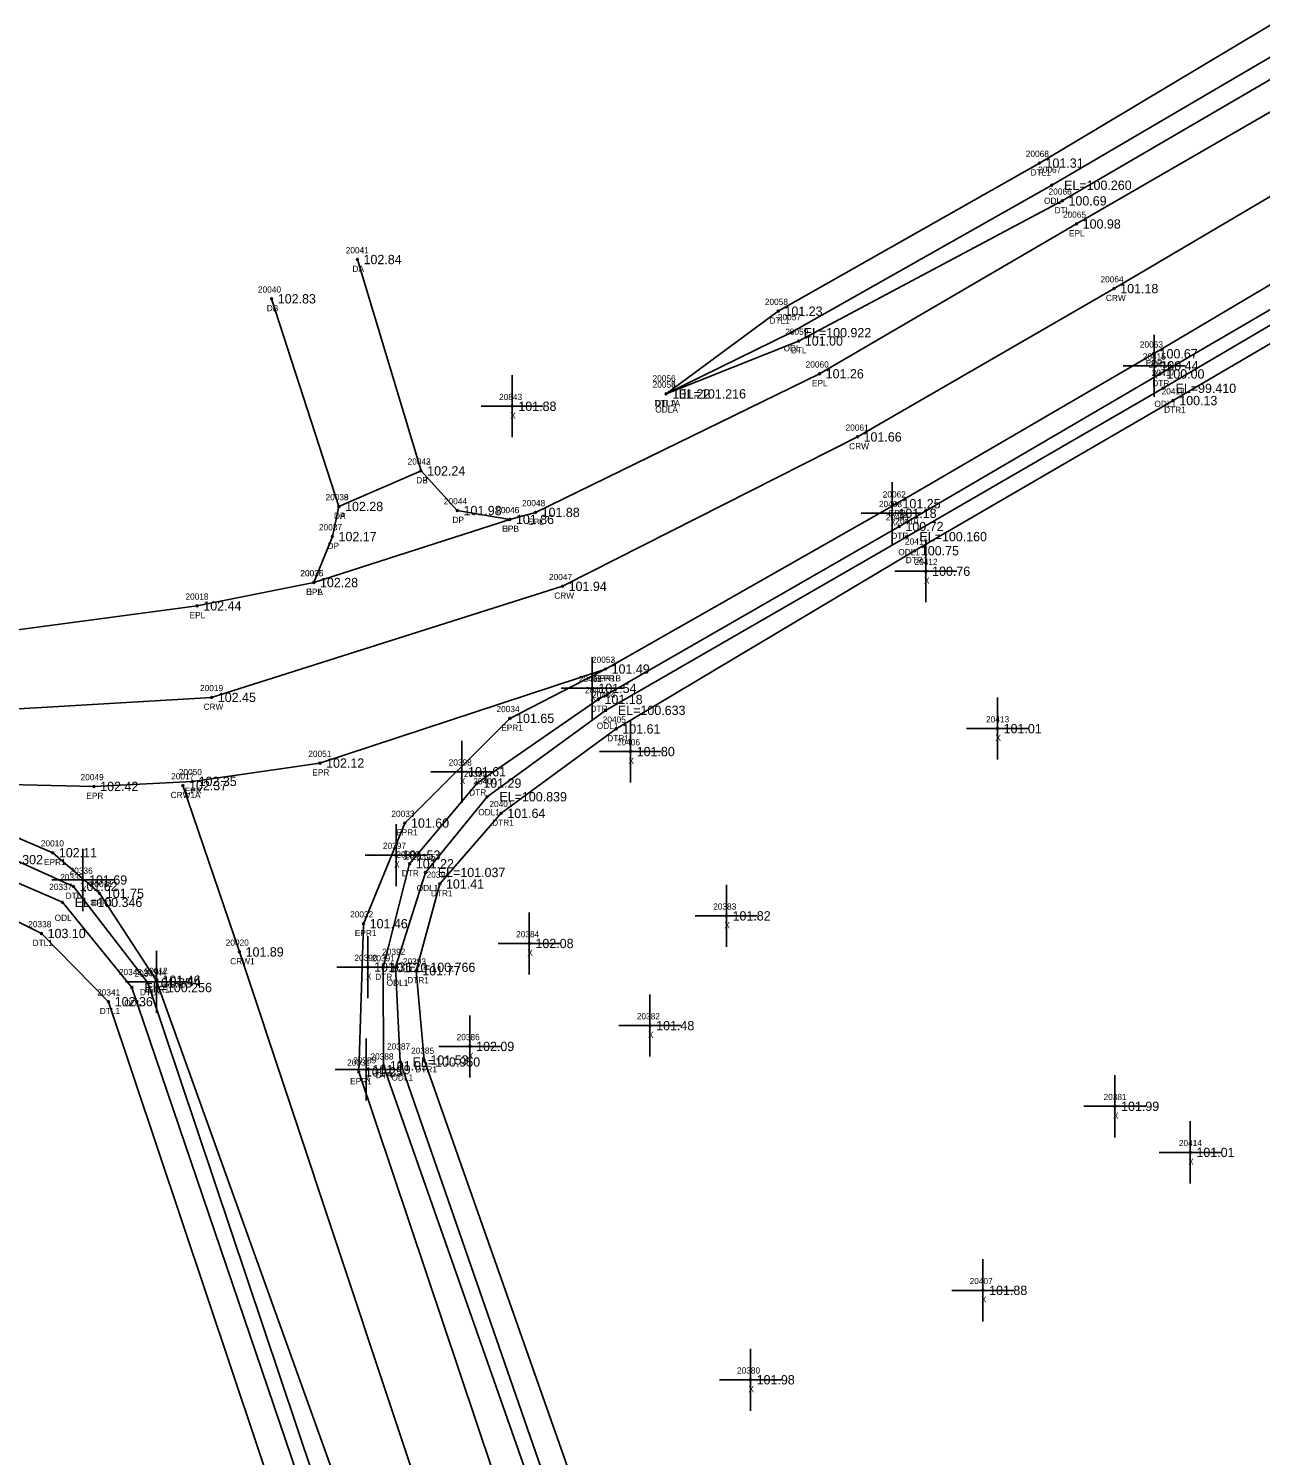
# Model space of a CAD drawing. Extents: x 2530197 to 2532051, y 935230 to 936631.
# Drawn here: x 2530440.5 to 2530638.9, y 935471.7 to 935701.6 of the extents above; entities that cross this region are included whole.
import ezdxf

# ---------------------------------------------------------------- set-up
doc = ezdxf.new("R2010")
doc.units = 0
for name, color, linetype in [('RD_DTM_BkLn1', 7, 'Continuous'), ('RD_EX_Driveway', 7, 'Continuous'), ('RD_EX_Driveway_txCode', 7, 'Continuous'), ('RD_EX_H2O', 7, 'Continuous'), ('RD_EX_H2O_txCode', 7, 'Continuous'), ('RD_EX_Misc', 7, 'Continuous'), ('RD_EX_Misc_txCode', 7, 'Continuous'), ('RD_EX_Road', 7, 'Continuous'), ('RD_EX_Road_txCode', 7, 'Continuous'), ('RD_EX_TX_Driveway_ELEV', 7, 'Continuous'), ('RD_EX_TX_H2O_ELEV', 7, 'Continuous'), ('RD_EX_TX_Misc_ELEV', 7, 'Continuous'), ('RD_EX_TX_Road_ELEV', 7, 'Continuous'), ('RD_HC_Survey_ELEV', 7, 'Continuous'), ('RD_HC_Survey_txCode', 7, 'Continuous'), ('RD_SMD_Locator', 7, 'Continuous')]:
    doc.layers.add(name, color=color, linetype=linetype)

msp = doc.modelspace()

# ---------------------------------------------------------------- linework, layer by layer
at = {"layer": 'RD_DTM_BkLn1'}
for points in [[(2530212.5, 935590.24), (2530312.97, 935590.25), (2530414.21, 935590.57), (2530470.01, 935593.88), (2530526.51, 935611.77), (2530574.01, 935635.84), (2530615.35, 935659.73), (2530701.7, 935710.7), (2530789.3, 935762.35), (2530874.46, 935813.14), (2530961.78, 935865.4), (2531046.63, 935916.04), (2531084.76, 935938.51)], [(2530465.37, 935579.66), (2530474.48, 935552.87), (2530506.43, 935456.79), (2530537.92, 935362.65), (2530570.08, 935267.03)]]:
    msp.add_lwpolyline(points, dxfattribs=at)
at = {"layer": 'RD_EX_Driveway'}
for p, q in [((2530493.48, 935664.42), (2530503.73, 935630.37)), ((2530490.5, 935624.63), (2530479.67, 935658.09))]:
    msp.add_line(p, q, dxfattribs=at)
msp.add_lwpolyline([(2530486.46, 935612.38), (2530489.45, 935619.79), (2530490.5, 935624.63), (2530503.73, 935630.37), (2530509.58, 935623.98), (2530518.02, 935622.55)], dxfattribs=at)
at = {"layer": 'RD_EX_H2O'}
for points in [[(2530543.2, 935642.77), (2530561.27, 935656.09), (2530603.32, 935679.95), (2530687.23, 935730.15), (2530719.54, 935749.07), (2530726.45, 935748.92)], [(2530543.2, 935642.77), (2530564.55, 935651.29), (2530607.02, 935673.87), (2530692.01, 935723.47), (2530725.54, 935743.2), (2530726.45, 935748.92)], [(2530543.2, 935642.77), (2530563.37, 935652.64), (2530605.31, 935676.39), (2530690.53, 935726.4), (2530722.23, 935744.95), (2530726.45, 935748.92)], [(2530585.61, 935271.89), (2530554.63, 935366.84), (2530523, 935462.44), (2530497.71, 935534.53), (2530497.63, 935550.35), (2530501.9, 935567.07), (2530512.76, 935580.06), (2530532.29, 935593.54), (2530580.75, 935621.41), (2530622.78, 935645.99), (2530706.38, 935694.8)], [(2530592.81, 935273.73), (2530561.2, 935369.39), (2530529.39, 935464.13), (2530504.24, 935535.46), (2530502.94, 935549.83), (2530506.75, 935563.82), (2530516.63, 935575.2), (2530535.16, 935588.8), (2530583.24, 935617.5), (2530624.86, 935641.7), (2530708.31, 935690.59), (2530708.33, 935693.17), (2530706.38, 935694.8)], [(2530587.86, 935272.38), (2530557.35, 935368.29), (2530525.38, 935463.03), (2530500.38, 935535.14), (2530499.61, 935550.4), (2530504.44, 935565.67), (2530514.36, 935577.87), (2530533.45, 935591.79), (2530582.01, 935619.78), (2530623.26, 935643.67), (2530705.7, 935692.18)], [(2530212.43, 935575.3), (2530312.61, 935575.57), (2530413.4, 935574.03), (2530431.14, 935570.94), (2530447.74, 935563.43), (2530459.72, 935547.88), (2530491.74, 935452.52), (2530522.77, 935357.57), (2530554.82, 935263)], [(2530212.28, 935572.05), (2530311.96, 935572.07), (2530413.48, 935570.72), (2530429.97, 935567.74), (2530445.97, 935560.86), (2530457.18, 935547.13), (2530489.52, 935451.8), (2530520.38, 935357.21), (2530552.97, 935262.56)], [(2530212.78, 935569.06), (2530311.54, 935568.98), (2530412.57, 935565.49), (2530428.32, 935562.93), (2530442.59, 935555.84), (2530453.4, 935544.85), (2530485.1, 935450.23), (2530516.56, 935356.42), (2530549.63, 935261.88)]]:
    msp.add_lwpolyline(points, dxfattribs=at)
at = {"layer": 'RD_EX_Misc'}
for p, q in [((2530621.82, 935642.3), (2530621.82, 935652.3)), ((2530616.82, 935647.3), (2530626.82, 935647.3)), ((2530518.41, 935635.78), (2530518.41, 935645.78)), ((2530513.41, 935640.78), (2530523.41, 935640.78)), ((2530579.63, 935618.53), (2530579.63, 935628.53)), ((2530574.63, 935623.53), (2530584.63, 935623.53)), ((2530585.05, 935609.2), (2530585.05, 935619.2)), ((2530580.05, 935614.2), (2530590.05, 935614.2)), ((2530531.3, 935590.34), (2530531.3, 935600.34)), ((2530526.3, 935595.34), (2530536.3, 935595.34)), ((2530596.57, 935583.85), (2530596.57, 935593.85)), ((2530537.47, 935580.15), (2530537.47, 935590.15)), ((2530591.57, 935588.85), (2530601.57, 935588.85)), ((2530510.3, 935576.9), (2530510.3, 935586.9)), ((2530532.47, 935585.15), (2530542.47, 935585.15)), ((2530505.3, 935581.9), (2530515.3, 935581.9)), ((2530499.72, 935563.47), (2530499.72, 935573.47)), ((2530449.27, 935559.46), (2530449.27, 935569.46)), ((2530494.72, 935568.47), (2530504.72, 935568.47)), ((2530444.27, 935564.46), (2530454.27, 935564.46)), ((2530552.91, 935553.68), (2530552.91, 935563.68)), ((2530521.17, 935549.23), (2530521.17, 935559.23)), ((2530547.91, 935558.68), (2530557.91, 935558.68)), ((2530495.17, 935545.42), (2530495.17, 935555.42)), ((2530461.12, 935543.06), (2530461.12, 935553.06)), ((2530516.17, 935554.23), (2530526.17, 935554.23)), ((2530490.17, 935550.42), (2530500.17, 935550.42)), ((2530456.12, 935548.06), (2530466.12, 935548.06)), ((2530540.61, 935536), (2530540.61, 935546)), ((2530511.61, 935532.65), (2530511.61, 935542.65)), ((2530535.61, 935541), (2530545.61, 935541)), ((2530494.92, 935528.91), (2530494.92, 935538.91)), ((2530506.61, 935537.65), (2530516.61, 935537.65)), ((2530489.92, 935533.91), (2530499.92, 935533.91)), ((2530615.49, 935523), (2530615.49, 935533)), ((2530610.49, 935528), (2530620.49, 935528)), ((2530627.62, 935515.58), (2530627.62, 935525.58)), ((2530622.62, 935520.58), (2530632.62, 935520.58)), ((2530594.24, 935493.35), (2530594.24, 935503.35)), ((2530589.24, 935498.35), (2530599.24, 935498.35)), ((2530556.79, 935478.94), (2530556.79, 935488.94)), ((2530551.79, 935483.94), (2530561.79, 935483.94))]:
    msp.add_line(p, q, dxfattribs=at)
at = {"layer": 'RD_EX_Road'}
for points in [[(2530213.13, 935600.16), (2530313.8, 935600.81), (2530414.15, 935601.13), (2530426.72, 935601.43), (2530429.46, 935603.55), (2530467.67, 935608.62), (2530486.46, 935612.38), (2530518.02, 935622.55), (2530522.16, 935623.68), (2530567.91, 935646.01), (2530609.3, 935670.15), (2530695.46, 935720.02), (2530775.85, 935769.27), (2530868.29, 935824.03), (2530924.84, 935856.95), (2530956.21, 935875.82), (2531040.72, 935926.38), (2531079.45, 935947.76)], [(2530212.44, 935579.72), (2530312.61, 935580.14), (2530402.98, 935580.64), (2530451.06, 935579.53), (2530466.91, 935580.35), (2530487.45, 935583.29), (2530533.43, 935598.45), (2530580.28, 935625.08), (2530621.69, 935649.23), (2530704.62, 935698.35), (2530718.67, 935706.38), (2530795.45, 935752.36), (2530871.33, 935796.67), (2530882.4, 935803.04), (2530947.17, 935842.26), (2530966, 935852.42), (2530992.72, 935868), (2531009.49, 935879.01), (2531052.39, 935904.85), (2531090.88, 935928.23)], [(2530591.21, 935242.46), (2530571.43, 935300.61), (2530549.4, 935366.29), (2530518.07, 935460.9), (2530493.7, 935533.55), (2530494.46, 935557.42), (2530501.12, 935573.63), (2530518.05, 935590.5), (2530533.43, 935598.45)], [(2530402.98, 935580.64), (2530413.62, 935578.66), (2530430.98, 935574.56), (2530444.41, 935568.86), (2530451.97, 935562.31), (2530461.09, 935548.32), (2530494.98, 935453.81), (2530526.54, 935359.14), (2530558.58, 935263.43)]]:
    msp.add_lwpolyline(points, dxfattribs=at)
at = {"layer": 'RD_SMD_Locator'}
for centre in [(2530603.32, 935679.95), (2530605.31, 935676.39), (2530607.02, 935673.87), (2530609.3, 935670.15), (2530493.48, 935664.42), (2530479.67, 935658.09), (2530615.35, 935659.73), (2530561.27, 935656.09), (2530563.37, 935652.64), (2530564.55, 935651.29), (2530621.69, 935649.23), (2530621.82, 935647.3), (2530567.91, 935646.01), (2530622.78, 935645.99), (2530543.2, 935642.77), (2530543.2, 935642.77), (2530543.2, 935642.77), (2530623.26, 935643.67), (2530624.86, 935641.7), (2530518.41, 935640.78), (2530574.01, 935635.84), (2530503.73, 935630.37), (2530503.73, 935630.37), (2530490.5, 935624.63), (2530490.5, 935624.63), (2530509.58, 935623.98), (2530522.16, 935623.68), (2530579.63, 935623.53), (2530580.28, 935625.08), (2530518.02, 935622.55), (2530518.02, 935622.55), (2530580.75, 935621.41), (2530489.45, 935619.79), (2530582.01, 935619.78), (2530583.24, 935617.5), (2530585.05, 935614.2), (2530486.46, 935612.38), (2530486.46, 935612.38), (2530526.51, 935611.77), (2530467.67, 935608.62), (2530533.43, 935598.45), (2530533.43, 935598.45), (2530470.01, 935593.88), (2530531.3, 935595.34), (2530532.29, 935593.54), (2530533.45, 935591.79), (2530518.05, 935590.5), (2530535.16, 935588.8), (2530596.57, 935588.85), (2530537.47, 935585.15), (2530487.45, 935583.29), (2530510.3, 935581.9), (2530451.06, 935579.53), (2530465.37, 935579.66), (2530466.91, 935580.35), (2530512.76, 935580.06), (2530514.36, 935577.87), (2530516.63, 935575.2), (2530501.12, 935573.63), (2530444.41, 935568.86), (2530499.72, 935568.47), (2530501.9, 935567.07), (2530504.44, 935565.67), (2530447.74, 935563.43), (2530449.27, 935564.46), (2530506.75, 935563.82), (2530451.97, 935562.31), (2530445.97, 935560.86), (2530494.46, 935557.42), (2530552.91, 935558.68), (2530442.59, 935555.84), (2530521.17, 935554.23), (2530474.48, 935552.87), (2530495.17, 935550.42), (2530497.63, 935550.35), (2530499.61, 935550.4), (2530502.94, 935549.83), (2530459.72, 935547.88), (2530461.09, 935548.32), (2530461.12, 935548.06), (2530457.18, 935547.13), (2530453.4, 935544.85), (2530540.61, 935541), (2530511.61, 935537.65), (2530493.7, 935533.55), (2530494.92, 935533.91), (2530497.71, 935534.53), (2530500.38, 935535.14), (2530504.24, 935535.46), (2530615.49, 935528), (2530627.62, 935520.58), (2530594.24, 935498.35), (2530556.79, 935483.94)]:
    msp.add_circle(centre, 0.15, dxfattribs=at)

# ---------------------------------------------------------------- texts
at = {"layer": 'RD_EX_Driveway_txCode'}
for s, p in [('20041', (2530491.61, 935665.42)), ('DA', (2530492.69, 935662.42)), ('20040', (2530477.47, 935659.09)), ('DB', (2530478.89, 935656.09)), ('20042', (2530501.57, 935631.37)), ('20043', (2530501.57, 935631.37)), ('DB', (2530502.95, 935628.37)), ('DP', (2530502.95, 935628.37)), ('20038', (2530488.35, 935625.63)), ('20039', (2530488.35, 935625.63)), ('20044', (2530507.42, 935624.98)), ('DA', (2530489.71, 935622.63)), ('DP', (2530489.72, 935622.63)), ('20045', (2530515.86, 935623.55)), ('20037', (2530487.29, 935620.79)), ('DP', (2530508.8, 935621.98)), ('DPB', (2530516.77, 935620.55)), ('DP', (2530488.67, 935617.79)), ('20036', (2530484.28, 935613.38)), ('DPA', (2530485.2, 935610.38))]:
    msp.add_text(s, height=1, dxfattribs=at).set_placement(p)
at = {"layer": 'RD_EX_H2O_txCode'}
for s, p in [('20068', (2530601.14, 935680.95)), ('DTL1', (2530601.92, 935677.95)), ('20067', (2530603.13, 935678.39)), ('ODL', (2530604.07, 935673.39)), ('20066', (2530604.81, 935674.87)), ('DTL', (2530605.77, 935671.87)), ('20058', (2530559.11, 935657.09)), ('20057', (2530561.21, 935654.64)), ('DTL1', (2530559.86, 935654.09)), ('20059', (2530562.39, 935652.29)), ('ODL', (2530562.12, 935649.64)), ('DTL', (2530563.3, 935649.29)), ('20416', (2530620.92, 935646.99)), ('20417', (2530621.42, 935645.67)), ('20056', (2530541.02, 935644.77)), ('20054', (2530541.04, 935643.77)), ('20055', (2530541.04, 935643.77)), ('DTR', (2530621.51, 935643.99)), ('DTL1A', (2530541.3, 935640.77)), ('DTLA', (2530541.46, 935640.77)), ('ODL1', (2530621.85, 935640.67)), ('20418', (2530623.02, 935642.7)), ('ODLA', (2530541.46, 935639.77)), ('DTR1', (2530623.42, 935639.7)), ('20409', (2530578.59, 935622.41)), ('20410', (2530580.13, 935621.78)), ('DTR', (2530579.48, 935619.41)), ('20411', (2530581.69, 935618.5)), ('ODL1', (2530580.6, 935616.78)), ('DTR1', (2530581.81, 935615.5)), ('20403', (2530530.14, 935594.54)), ('20404', (2530531.3, 935593.79)), ('DTR', (2530531.03, 935591.54)), ('ODL1', (2530532.04, 935588.79)), ('20405', (2530533, 935589.8)), ('DTR1', (2530533.73, 935586.8)), ('20399', (2530510.64, 935581.06)), ('20400', (2530512.16, 935579.87)), ('DTR', (2530511.49, 935578.06)), ('ODL1', (2530512.95, 935574.87)), ('20401', (2530514.75, 935576.2)), ('DTR1', (2530515.19, 935573.2)), ('20396', (2530499.76, 935568.07)), ('20395', (2530502.32, 935567.67)), ('DTR', (2530500.63, 935565.07)), ('20394', (2530504.63, 935564.82)), ('20337', (2530443.85, 935562.86)), ('20335', (2530445.62, 935564.43)), ('ODL1', (2530503.03, 935562.67)), ('DTL', (2530446.5, 935561.43)), ('DTR1', (2530505.32, 935561.82)), ('20338', (2530440.47, 935556.84)), ('ODL', (2530444.73, 935557.86)), ('DTL1', (2530441.18, 935553.84)), ('20391', (2530495.8, 935551.35)), ('20392', (2530497.49, 935552.4)), ('20342', (2530455.07, 935549.13)), ('20343', (2530457.6, 935548.88)), ('20393', (2530500.82, 935550.83)), ('DTR', (2530496.36, 935548.35)), ('ODL1', (2530498.2, 935547.4)), ('DTR1', (2530501.51, 935547.83)), ('20341', (2530451.56, 935545.85)), ('ODL', (2530455.94, 935544.13)), ('DTL', (2530458.47, 935545.88)), ('DTL1', (2530451.99, 935542.85)), ('20388', (2530495.59, 935535.53)), ('20387', (2530498.26, 935537.14)), ('20385', (2530502.13, 935536.46)), ('DTR1', (2530502.81, 935533.46)), ('DTR', (2530496.44, 935532.53)), ('ODL1', (2530498.97, 935532.14))]:
    msp.add_text(s, height=1, dxfattribs=at).set_placement(p)
at = {"layer": 'RD_EX_Misc_txCode'}
for s, p in [('20415', (2530619.98, 935648.3)), ('X', (2530621.5, 935645.3)), ('20843', (2530516.3, 935641.78)), ('X', (2530518.1, 935638.78)), ('20408', (2530577.48, 935624.53)), ('X', (2530579.32, 935621.53)), ('20412', (2530583.21, 935615.2)), ('X', (2530584.73, 935612.2)), ('20402', (2530529.14, 935596.34)), ('X', (2530530.98, 935593.34)), ('20413', (2530594.74, 935589.85)), ('20406', (2530535.29, 935586.15)), ('X', (2530596.26, 935586.85)), ('20398', (2530508.19, 935582.9)), ('X', (2530537.15, 935583.15)), ('X', (2530509.99, 935579.9)), ('20397', (2530497.6, 935569.47)), ('20336', (2530447.13, 935565.46)), ('X', (2530499.4, 935566.47)), ('X', (2530448.96, 935562.46)), ('20383', (2530550.79, 935559.68)), ('X', (2530552.6, 935556.68)), ('20384', (2530519.05, 935555.23)), ('20390', (2530493.01, 935551.42)), ('X', (2530520.85, 935552.23)), ('20344', (2530459, 935549.06)), ('X', (2530494.86, 935548.42)), ('X', (2530460.81, 935546.06)), ('20382', (2530538.49, 935542)), ('20386', (2530509.47, 935538.65)), ('X', (2530540.3, 935539)), ('20389', (2530492.8, 935534.91)), ('X', (2530511.29, 935535.65)), ('X', (2530494.61, 935531.91)), ('20381', (2530613.66, 935529)), ('X', (2530615.18, 935526)), ('20414', (2530625.79, 935521.58)), ('X', (2530627.31, 935518.58)), ('20407', (2530592.09, 935499.35)), ('X', (2530593.93, 935496.35)), ('20380', (2530554.63, 935484.94)), ('X', (2530556.47, 935481.94))]:
    msp.add_text(s, height=1, dxfattribs=at).set_placement(p)
at = {"layer": 'RD_EX_Road_txCode'}
for s, p in [('20065', (2530607.12, 935671.15)), ('EPL', (2530608.09, 935668.15)), ('20063', (2530619.51, 935650.23)), ('20060', (2530565.69, 935647.01)), ('EPR', (2530620.47, 935647.23)), ('EPL', (2530566.7, 935644.01)), ('20048', (2530520.01, 935624.68)), ('20062', (2530578.1, 935626.08)), ('20046', (2530515.84, 935623.55)), ('EPR', (2530579.05, 935623.08)), ('EPL', (2530516.82, 935620.55)), ('EPL', (2530520.96, 935621.68)), ('20035', (2530484.31, 935613.38)), ('20018', (2530465.79, 935609.62)), ('EPL', (2530485.26, 935610.38)), ('EPL', (2530466.46, 935606.62)), ('20052', (2530531.27, 935599.45)), ('20053', (2530531.27, 935599.45)), ('EPR1B', (2530531.56, 935596.45)), ('EPR', (2530532.2, 935596.45)), ('20034', (2530515.89, 935591.5)), ('EPR1', (2530516.65, 935588.5)), ('20051', (2530485.58, 935584.29)), ('20050', (2530464.72, 935581.35)), ('EPR', (2530486.22, 935581.29)), ('20049', (2530448.9, 935580.53)), ('EPR', (2530449.83, 935577.53)), ('EPR', (2530465.68, 935578.35)), ('20033', (2530498.96, 935574.63)), ('20010', (2530442.5, 935569.86)), ('EPR1', (2530499.72, 935571.63)), ('EPR1', (2530443.01, 935566.86)), ('20011', (2530450.38, 935563.31)), ('EPR1', (2530450.57, 935560.31)), ('20032', (2530492.31, 935558.42)), ('EPR1', (2530493.07, 935555.42)), ('20012', (2530459.21, 935549.32)), ('EPR1', (2530459.69, 935546.32)), ('20031', (2530491.83, 935534.55)), ('EPR1', (2530492.31, 935531.55))]:
    msp.add_text(s, height=1, dxfattribs=at).set_placement(p)
at = {"layer": 'RD_EX_TX_Driveway_ELEV'}
for s, p in [('102.84', (2530494.48, 935663.67)), ('102.83', (2530480.67, 935657.34)), ('102.24', (2530504.73, 935629.62)), ('102.24', (2530504.73, 935629.62)), ('102.28', (2530491.5, 935623.88)), ('102.28', (2530491.5, 935623.88)), ('101.98', (2530510.58, 935623.23)), ('101.86', (2530519.02, 935621.8)), ('102.17', (2530490.45, 935619.04)), ('102.28', (2530487.46, 935611.63))]:
    msp.add_text(s, height=1.5, dxfattribs=at).set_placement(p)
at = {"layer": 'RD_EX_TX_H2O_ELEV'}
for s, p in [('101.31', (2530604.32, 935679.2)), ('EL=100.260', (2530607.31, 935675.64)), ('100.69', (2530608.02, 935673.12)), ('101.23', (2530562.27, 935655.34)), ('EL=100.922', (2530565.37, 935651.89)), ('101.00', (2530565.55, 935650.54)), ('100.00', (2530623.78, 935645.24)), ('EL=99.410', (2530625.26, 935642.92)), ('101.22', (2530544.2, 935642.02)), ('101.22', (2530544.2, 935642.02)), ('EL=101.216', (2530545.2, 935642.02)), ('100.13', (2530625.86, 935640.95)), ('100.72', (2530581.75, 935620.66)), ('EL=100.160', (2530584.01, 935619.03)), ('100.75', (2530584.24, 935616.75)), ('101.18', (2530533.29, 935592.79)), ('EL=100.633', (2530535.45, 935591.04)), ('101.61', (2530536.16, 935588.05)), ('101.29', (2530513.76, 935579.31)), ('EL=100.839', (2530516.36, 935577.12)), ('101.64', (2530517.63, 935574.45)), ('EL=100.302', (2530431.97, 935566.99)), ('101.22', (2530502.9, 935566.32)), ('EL=101.037', (2530506.44, 935564.92)), ('101.62', (2530448.74, 935562.68)), ('101.41', (2530507.75, 935563.07)), ('EL=100.346', (2530447.97, 935560.11)), ('103.10', (2530443.59, 935555.09)), ('101.20', (2530498.63, 935549.6)), ('EL=100.766', (2530501.61, 935549.65)), ('101.77', (2530503.94, 935549.08)), ('EL=100.256', (2530459.18, 935546.38)), ('101.25', (2530460.72, 935547.13)), ('102.36', (2530454.4, 935544.1)), ('EL=100.950', (2530502.38, 935534.39)), ('101.53', (2530505.24, 935534.71)), ('101.09', (2530498.71, 935533.78))]:
    msp.add_text(s, height=1.5, dxfattribs=at).set_placement(p)
at = {"layer": 'RD_EX_TX_Misc_ELEV'}
for s, p in [('100.44', (2530622.82, 935646.55)), ('101.88', (2530519.41, 935640.03)), ('101.18', (2530580.63, 935622.78)), ('100.76', (2530586.05, 935613.45)), ('101.54', (2530532.3, 935594.59)), ('101.01', (2530597.57, 935588.1)), ('101.80', (2530538.47, 935584.4)), ('101.61', (2530511.3, 935581.15)), ('101.53', (2530500.72, 935567.72)), ('101.69', (2530450.27, 935563.71)), ('101.82', (2530553.91, 935557.93)), ('102.08', (2530522.17, 935553.48)), ('101.36', (2530496.17, 935549.67)), ('101.44', (2530462.12, 935547.31)), ('101.48', (2530541.61, 935540.25)), ('102.09', (2530512.61, 935536.9)), ('101.19', (2530495.92, 935533.16)), ('101.99', (2530616.49, 935527.25)), ('101.01', (2530628.62, 935519.83)), ('101.88', (2530595.24, 935497.6)), ('101.98', (2530557.79, 935483.19))]:
    msp.add_text(s, height=1.5, dxfattribs=at).set_placement(p)
at = {"layer": 'RD_EX_TX_Road_ELEV'}
for s, p in [('100.98', (2530610.3, 935669.4)), ('100.67', (2530622.69, 935648.48)), ('101.26', (2530568.91, 935645.26)), ('101.25', (2530581.28, 935624.33)), ('101.86', (2530519.02, 935621.8)), ('101.88', (2530523.16, 935622.93)), ('102.28', (2530487.46, 935611.63)), ('102.44', (2530468.67, 935607.87)), ('101.49', (2530534.43, 935597.7)), ('101.49', (2530534.43, 935597.7)), ('101.65', (2530519.05, 935589.75)), ('102.12', (2530488.45, 935582.54)), ('102.42', (2530452.06, 935578.78)), ('102.35', (2530467.91, 935579.6)), ('101.60', (2530502.12, 935572.88)), ('102.11', (2530445.41, 935568.11)), ('101.75', (2530452.97, 935561.56)), ('101.46', (2530495.46, 935556.67)), ('101.46', (2530462.09, 935547.57)), ('101.25', (2530494.7, 935532.8))]:
    msp.add_text(s, height=1.5, dxfattribs=at).set_placement(p)
at = {"layer": 'RD_HC_Survey_ELEV'}
for s, p in [('101.18', (2530616.35, 935658.98)), ('101.66', (2530575.01, 935635.09)), ('101.94', (2530527.51, 935611.02)), ('102.45', (2530471.01, 935593.13)), ('102.37', (2530466.37, 935578.91)), ('101.89', (2530475.48, 935552.12))]:
    msp.add_text(s, height=1.5, dxfattribs=at).set_placement(p)
at = {"layer": 'RD_HC_Survey_txCode'}
for s, p in [('20064', (2530613.17, 935660.73)), ('CRW', (2530614.04, 935657.73)), ('20061', (2530572.11, 935636.84)), ('CRW', (2530572.69, 935633.84)), ('20047', (2530524.35, 935612.77)), ('CRW', (2530525.19, 935609.77)), ('20019', (2530468.14, 935594.88)), ('CRW', (2530468.7, 935591.88)), ('20017', (2530463.49, 935580.66)), ('CRW1A', (2530463.4, 935577.66)), ('20020', (2530472.28, 935553.87)), ('CRW1', (2530473, 935550.87))]:
    msp.add_text(s, height=1, dxfattribs=at).set_placement(p)

doc.saveas('drawing.dxf')
